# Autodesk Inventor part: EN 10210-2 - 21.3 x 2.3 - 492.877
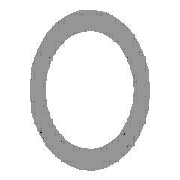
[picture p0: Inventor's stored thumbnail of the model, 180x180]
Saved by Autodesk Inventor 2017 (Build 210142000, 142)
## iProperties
Created: 2017-11
Part Number: EN 10210-2 - 21.3 x 2.3 - 492.877
Material: Steel, Mild
Description: Pipe
Document SubType Name: Modeling
Standard: DIN
Designer: iusti
Standard Revision: 2006-07
Standards Organization: DIN
Language: en-US
Size Designation: 21.3 x 2.3
Categories: <MemberInstance><Categories><Category DisplayName="Structural Shapes" InternalName="089c4875-fa83-4c05-b084-43b9cc11f5ed" Mnemonic="GRDR"><CategoryParameter Dis
Stock Number: 21.3 x 2.3
Density: 7.85 g/cm^3
Appearance: Semi-Polished
_CCFamilyMember: 1
_CCFamilyDisplayName: DIN EN 10210-2 - Pipe
_FrameMemberDoc: Frame Member File
_Version: 15.0.0
_GetPNFromCC: 1
G_L: 492.877 mm
G_W: 21.300 mm
G_H: 21.300 mm
IsCustomPart: 1
Author: iusti
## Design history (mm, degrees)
node "Start plane"
node "End plane"
sketch "Sketch"
  geometry: C1 r 8.35 at (0, 0); C2 r 10.65 at (0, 0); 2 further points
  constraints: 3 coincident, 2 centre point
  dimensions: "d0" = 21.3 diameter of C2 (= G_H); "d1" = 2.3 radial gap between concentric circles of C2 C1 (= G_T)
extrude "Body" new body sketch "Sketch" stored distance "d2" = 492.87692 (= G_L); taper "d3" = 0 deg
node "Driven Length"
  sketch "Sketch3"
    geometry: L1 (0, 0)-(10, 0) reference
    constraints: 2 end point, 1 horizontal
  workplane "Work Plane3"
  sketch "Sketch4"
    geometry: L1 (-2, 0)-(12, 0) reference; L2 (-2, 492.877)-(12, 492.877) reference
    dimensions: "d7" = 492.87692 distance between parallel lines of L1 L2 (derived)
body "Solid1"
other parameters: "G_H" = 21.3 [user parameter; used in 1 equation term], "G_T" = 2.3 [user parameter; used in 1 equation term], "G_L" = 492.87692 (= d7) [user parameter; used in 1 equation term], "G_OFFSET_START" = 0 [user parameter; used in 1 equation term], "G_OFFSET_END" = 0 [user parameter; used in 1 equation term], "d4" = 0 (computed from G_OFFSET_START), "d5" = 492.87692 (= G_OFFSET_END + B_L), "B_L" = 492.87692 [user parameter; used in 1 equation term], "d6" = 90 deg
